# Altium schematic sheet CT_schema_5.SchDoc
size 479 x 328 mm
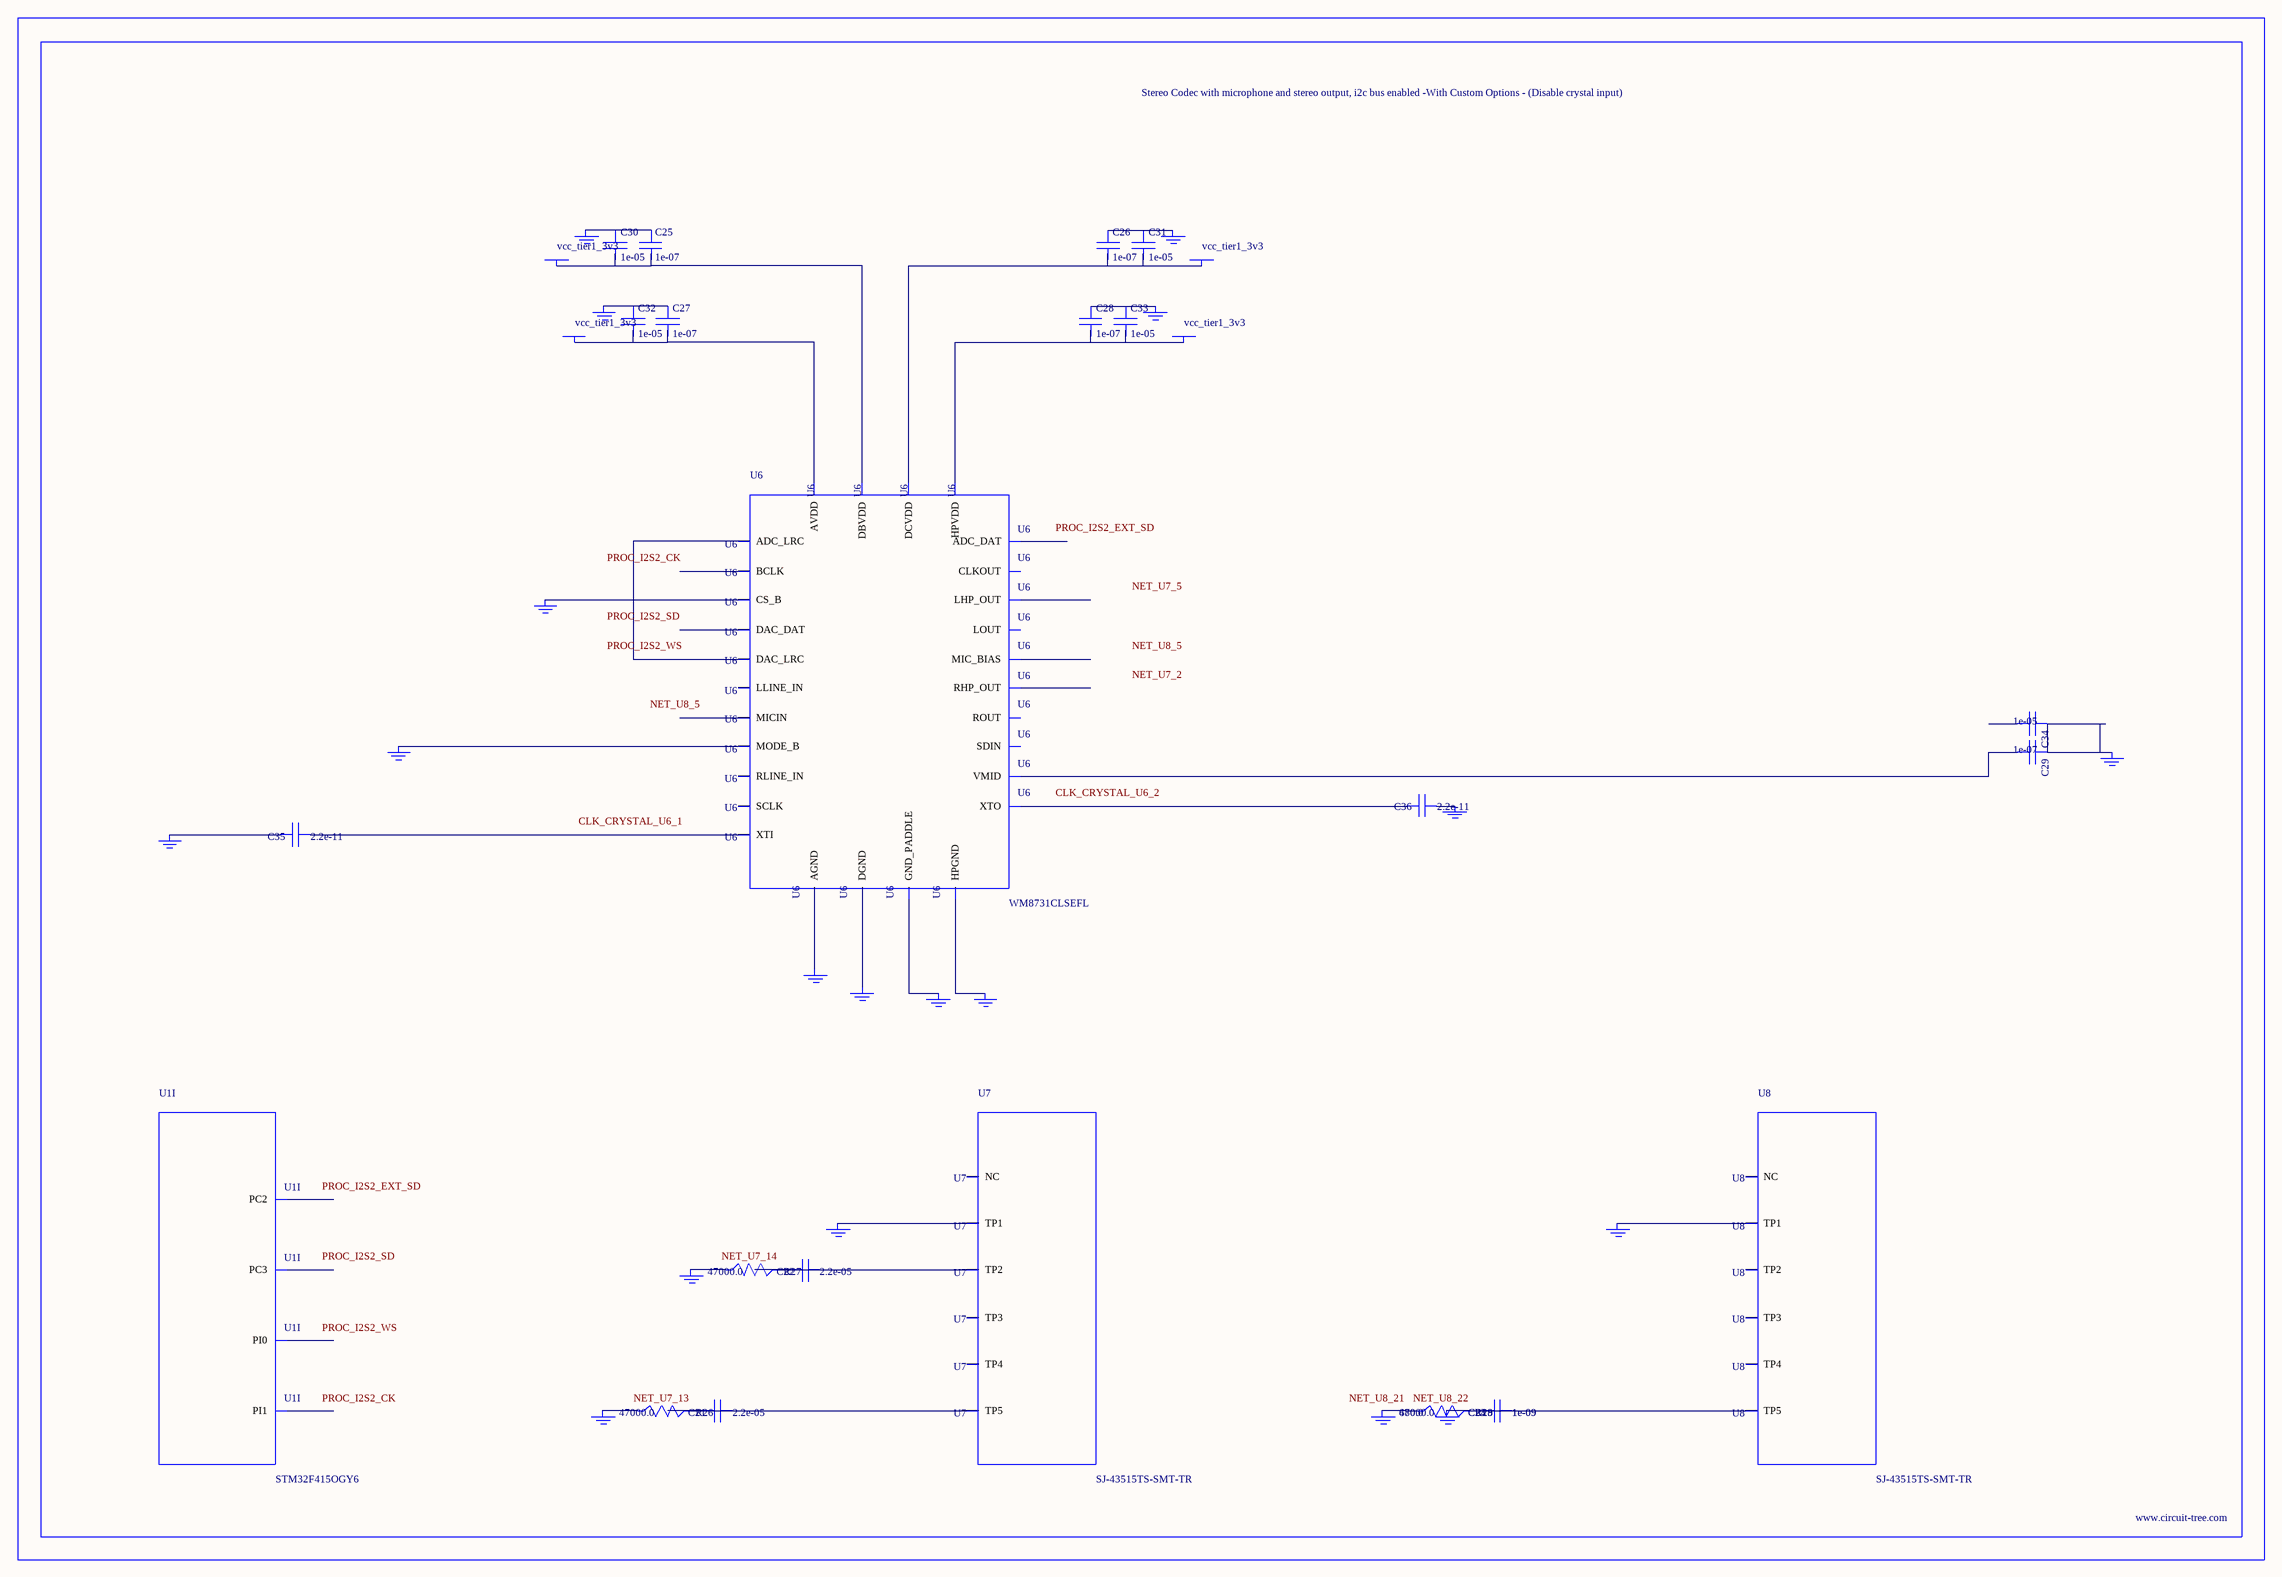
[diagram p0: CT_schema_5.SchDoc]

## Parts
BORDER4  (no value)
C21  2.2e-05  [C1210]
C22  2.2e-05  [C1210]
C23  1e-09  [C0402]
C24  1e-09  [C0402]
C25  1e-07  [C0402]
C26  1e-07  [C0402]
C27  1e-07  [C0402]
C28  1e-07  [C0402]
C29  1e-07  [C0402]
C30  1e-05  [C0805]
C31  1e-05  [C0805]
C32  1e-05  [C0805]
C33  1e-05  [C0805]
C34  1e-05  [C0805]
C35  2.2e-11  [C0402]
C36  2.2e-11  [C0402]
GND_INSTANCE_4_0  (no value)
GND_INSTANCE_4_1  (no value)
GND_INSTANCE_4_2  (no value)
GND_INSTANCE_4_3  (no value)
GND_INSTANCE_4_4  (no value)
GND_INSTANCE_4_5  (no value)
GND_INSTANCE_4_6  (no value)
GND_INSTANCE_4_7  (no value)
GND_INSTANCE_4_8  (no value)
GND_INSTANCE_4_9  (no value)
GND_INSTANCE_4_10  (no value)
GND_INSTANCE_4_11  (no value)
GND_INSTANCE_4_12  (no value)
GND_INSTANCE_4_13  (no value)
GND_INSTANCE_4_14  (no value)
GND_INSTANCE_4_15  (no value)
GND_INSTANCE_4_16  (no value)
GND_INSTANCE_4_17  (no value)
GND_INSTANCE_4_18  (no value)
POWER_INSTANCE_4_0  vcc_tier1_3v3
POWER_INSTANCE_4_1  vcc_tier1_3v3
POWER_INSTANCE_4_2  vcc_tier1_3v3
POWER_INSTANCE_4_3  vcc_tier1_3v3
R26  47000.0  [R0603]
R27  47000.0  [R0603]
R28  47000.0  [R0603]
R29  680.0  [R0603]
U1  STM32F415OGY6  [WLCSP90]  (part I of 9)
U6  WM8731CLSEFL  [QFN-28]
U7  SJ-43515TS-SMT-TR  [SJ-43515TS-SMT-TR]
U8  SJ-43515TS-SMT-TR  [SJ-43515TS-SMT-TR]

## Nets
NetC21_1: C21.1 C21.2 R26.2 U7.5(TP5)
NetC22_1: C22.1 C22.2 R27.2 U7.2(TP2)
NetC23_1: C23.1 C23.2 C24.1 C24.2 GND_INSTANCE_4_18.0(GND) R28.2 R29.2 U8.5(TP5)
NetC25_1: C25.1 C30.1 GND_INSTANCE_4_3.0(GND)
NetC25_2: C25.2 C30.2 POWER_INSTANCE_4_1.0(PWR) U6.5(DBVDD)
NetC26_1: C26.1 C31.1 GND_INSTANCE_4_2.0(GND)
NetC26_2: C26.2 C31.2 POWER_INSTANCE_4_0.0(PWR) U6.3(DCVDD)
NetC27_1: C27.1 C32.1 GND_INSTANCE_4_6.0(GND)
NetC27_2: C27.2 C32.2 POWER_INSTANCE_4_3.0(PWR) U6.18(AVDD)
NetC28_1: C28.1 C33.1 GND_INSTANCE_4_4.0(GND)
NetC28_2: C28.2 C33.2 POWER_INSTANCE_4_2.0(PWR) U6.12(HPVDD)
NetC29_1: C29.1 C34.1 GND_INSTANCE_4_7.0(GND)
NetC29_2: C29.2 U6.20(VMID)
NetC35_1: C35.1 U6.1(XTI)
NetC35_2: C35.2 GND_INSTANCE_4_0.0(GND)
NetC36_1: C36.1 GND_INSTANCE_4_1.0(GND)
NetC36_2: C36.2 U6.2(XTO)
NetGND_INSTANCE_4_5_0: GND_INSTANCE_4_5.0(GND) U6.15(HPGND)
NetGND_INSTANCE_4_8_0: GND_INSTANCE_4_8.0(GND) U6.25(MODE_B)
NetGND_INSTANCE_4_9_0: GND_INSTANCE_4_9.0(GND) U6.26(CS_B)
NetGND_INSTANCE_4_10_0: GND_INSTANCE_4_10.0(GND) U6.29(GND_PADDLE)
NetGND_INSTANCE_4_11_0: GND_INSTANCE_4_11.0(GND) U6.4(DGND)
NetGND_INSTANCE_4_12_0: GND_INSTANCE_4_12.0(GND) U6.19(AGND)
NetGND_INSTANCE_4_13_0: GND_INSTANCE_4_13.0(GND) U7.1(TP1)
NetGND_INSTANCE_4_14_0: GND_INSTANCE_4_14.0(GND) R27.1
NetGND_INSTANCE_4_15_0: GND_INSTANCE_4_15.0(GND) R26.1
NetGND_INSTANCE_4_16_0: GND_INSTANCE_4_16.0(GND) U8.1(TP1)
NetGND_INSTANCE_4_17_0: GND_INSTANCE_4_17.0(GND) R28.1 R29.1
NetU6_9: U6.9(DAC_LRC) U6.11(ADC_LRC)

Not connected (* = marked no-connect by the designer): C34 2; U1 B2(PI1) C3(PI0) D10(PC2) E9(PC3); U6 6(CLKOUT) 7(BCLK) 8(DAC_DAT) 10(ADC_DAT) 13(LHP_OUT) 14(RHP_OUT) 16(LOUT) 17(ROUT) 21(MIC_BIAS) 22(MICIN) 23(RLINE_IN) 24(LLINE_IN) 27(SDIN) 28(SCLK); U7 3(TP3) 4(TP4) 6(NC); U8 2(TP2) 3(TP3) 4(TP4) 6(NC)

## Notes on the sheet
- Labels drawn without touching a wire or pin: CLK_CRYSTAL_U6_1, CLK_CRYSTAL_U6_2, NET_U7_2, NET_U7_5, NET_U7_13, NET_U7_14, NET_U8_5, NET_U8_21, NET_U8_22, PROC_I2S2_CK, PROC_I2S2_EXT_SD, PROC_I2S2_SD, PROC_I2S2_WS

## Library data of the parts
BORDER4 = BORDER_PAGE4
C21 C22 = C1210C224K5RACTU
C23 C24 = C0402C102K3RAC
C25-C29 = C0402C104K3RACTU
C30-C34 = C0805C106K8RACTU
C35 C36 = C0402C220K3RAC
GND_INSTANCE_4_0-GND_INSTANCE_4_18 = GND
POWER_INSTANCE_4_0-POWER_INSTANCE_4_3 = PWR
R26-R28 = RC0603JR-0747KL
R29 = RC0603JR-07680RL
